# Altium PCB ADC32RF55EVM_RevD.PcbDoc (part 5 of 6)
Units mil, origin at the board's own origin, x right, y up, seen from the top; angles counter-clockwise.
Board outline 4190 x 2750 mil, 14 copper layers (Top Copper, Layer 2 (GND1), Layer 3 (PWR1), Layer 4 (GND2, Layer 5 (PWR2), Layer 6 (GND3), Layer 7 (SIG1), Layer 8 (GND4), Layer 9 (GND5), Layer 10 (SIG2), Layer 11 (GND6), Layer 12 (PWR3), Layer 13 (GND7), Bottom Copper), stack 58.6 mil thick; 427 components, 558 nets, 1902 pads, 1008 vias.
Unrouted connection lines stored in the file: 51.
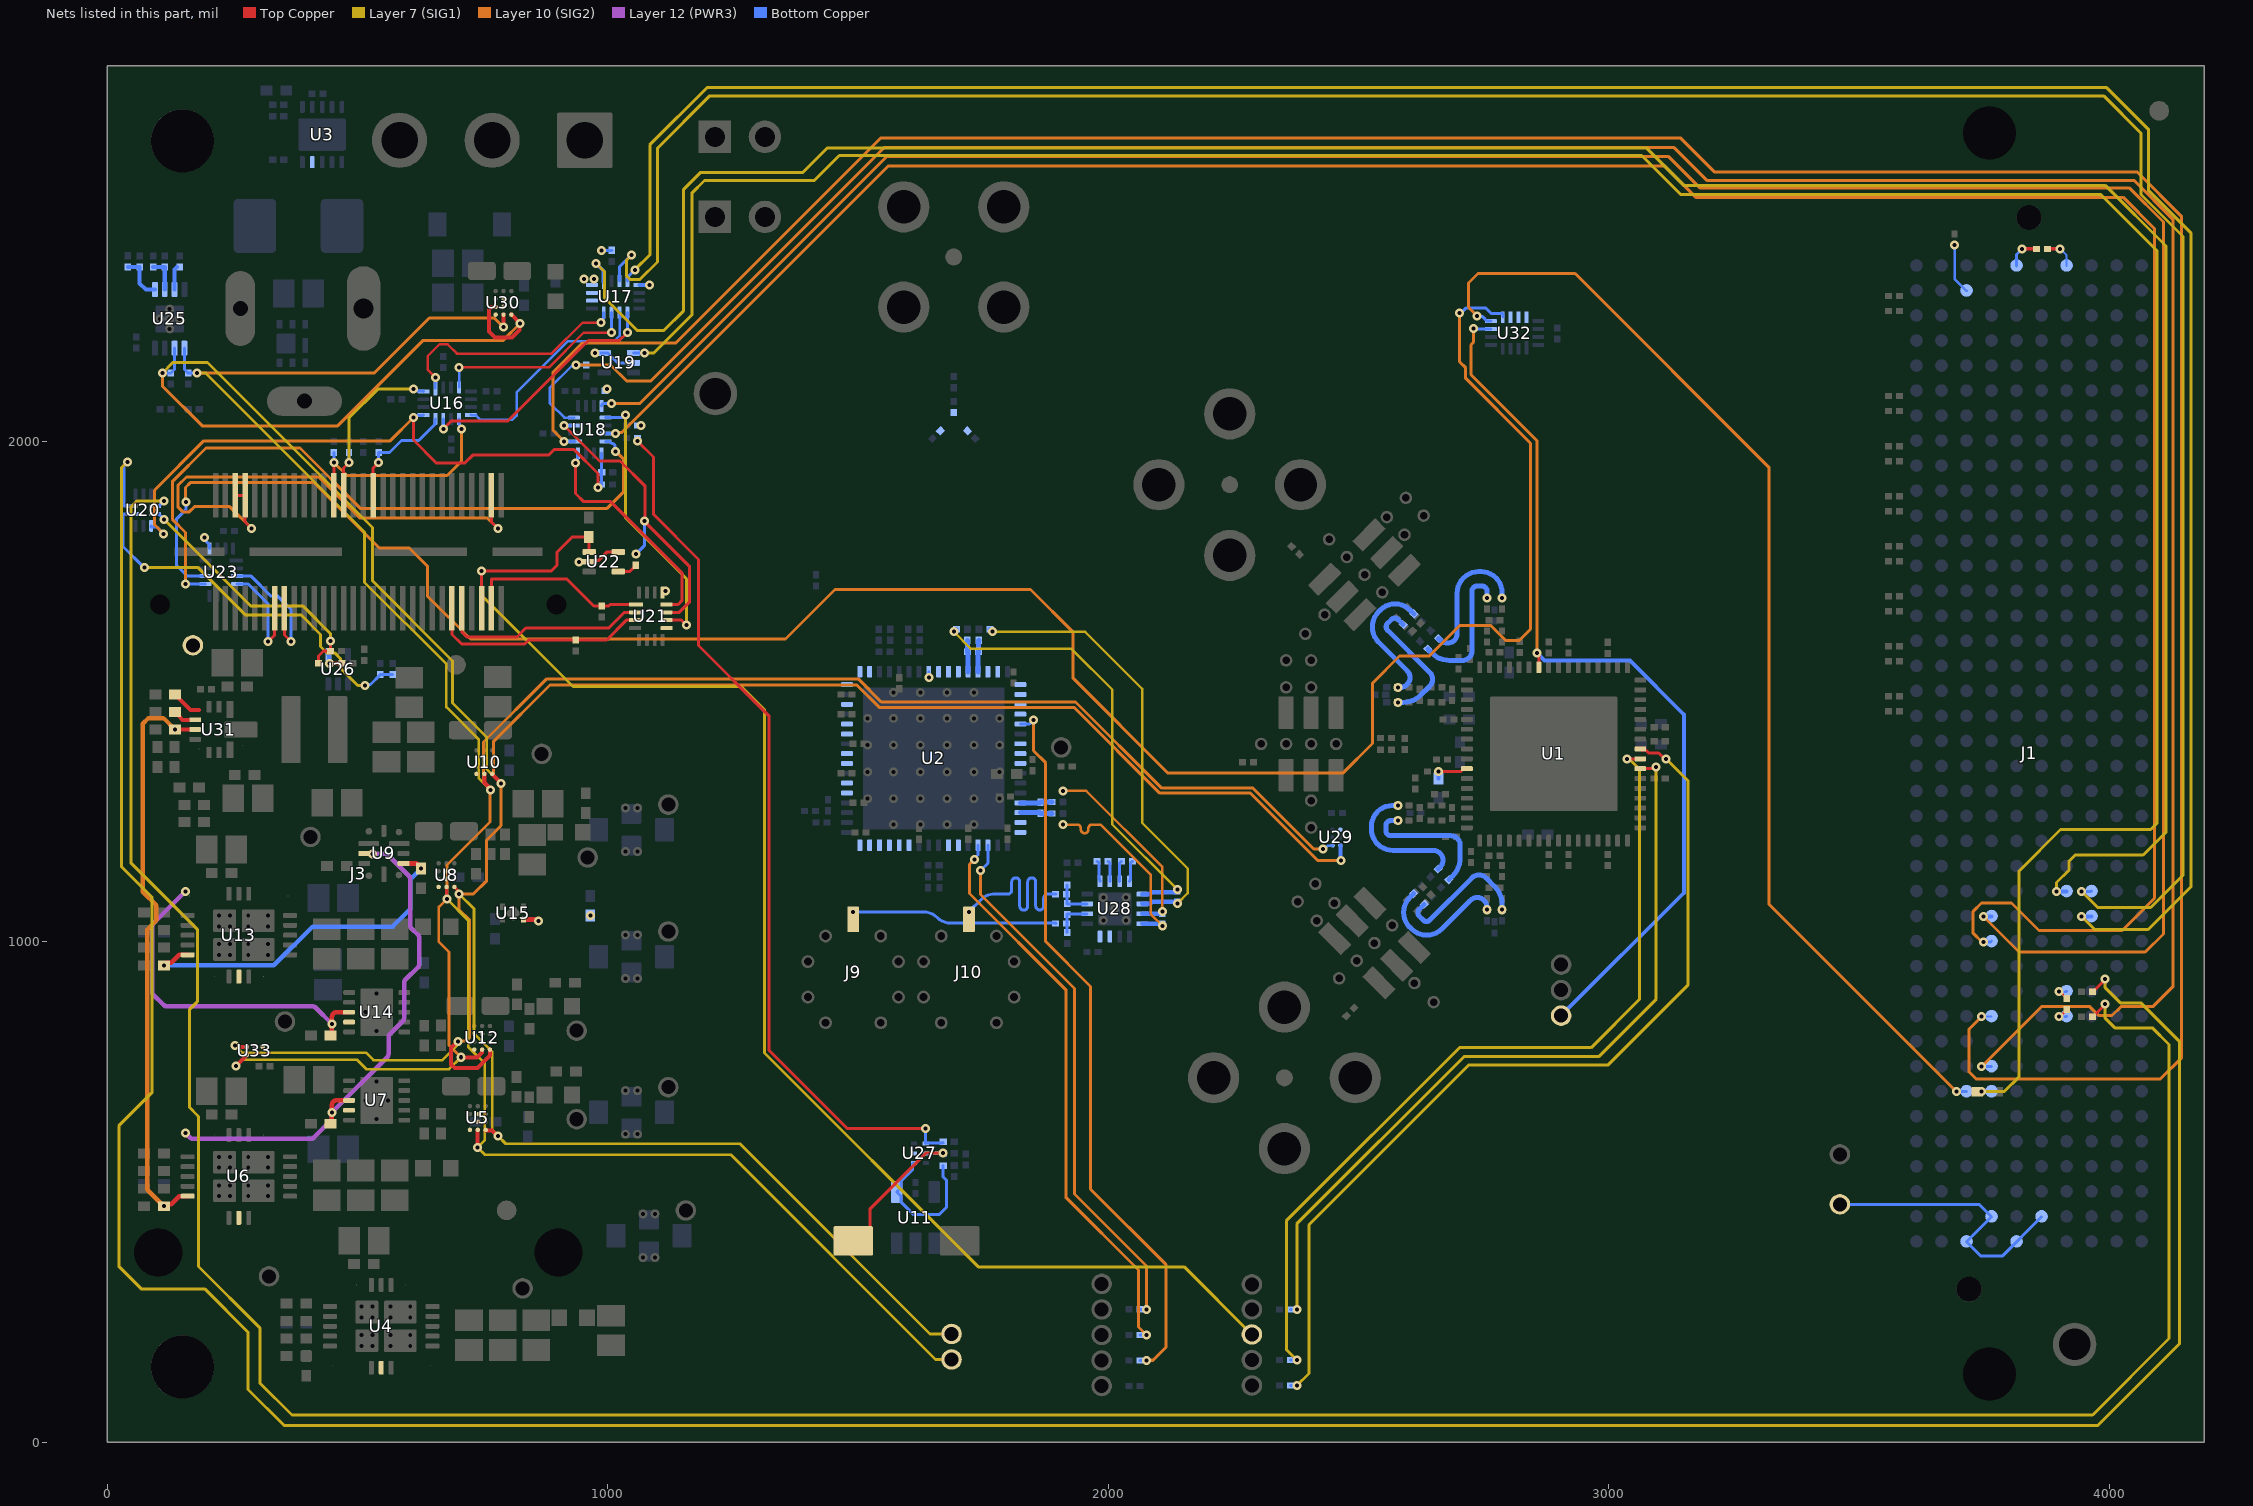
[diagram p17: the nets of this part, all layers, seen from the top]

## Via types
v1: diameter 18, hole 8, Top Copper to Bottom Copper, tented both sides, 1004 vias
v2: diameter 25.75, hole 15.75, Top Copper to Bottom Copper, tented both sides, 4 vias

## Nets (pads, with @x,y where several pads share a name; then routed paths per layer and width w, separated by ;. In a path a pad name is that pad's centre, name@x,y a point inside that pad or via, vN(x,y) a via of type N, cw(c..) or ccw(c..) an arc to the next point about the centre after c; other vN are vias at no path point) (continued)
NetR80_1: R80.1 R97.1 U26.4 | length 43
  Top Copper w8: v1(444,1555.95) R97.1@469,1555.95
  Bottom Copper w8: U26.4@441.63,1573 442.82,1571.82 442.82,1557.14 v1(444,1555.95)
NetR81_2: R81.2 R83.2 U16.13 U18.13 U20.8 | length 1281.3
  Top Copper w6: v1(612,2047.19) 612,2002 658,1956 714,1956 730,1972 881.63,1972 892.63,1983 933,1983 980.73,1935.27 v1(980.73,1907.18)
  Layer 10 (SIG2) w6: v1(112.29,1814.78) 94.22,1832.85 94.22,1901.8 192.88,2000.45 565.26,2000.45 v1(612,2047.19)
  Bottom Copper w6: U20.8@87.75,1830.5 87.75,1828.4 98.68,1828.4 v1(112.29,1814.78) ; v1(612,2047.19) 615.24,2047.19 619.31,2051.25 631.06,2051.25 U16.13@632,2052.19 ; R83.2@987.81,1913.48 987.93,1913.6 U18.13@987.93,1975.91
NetR88_1: R88.1 U22.4 | length 40.6
  Top Copper w6: U22.4@1021.13,1739.32 1044.13,1739.32 1056,1751.19 R88.1@1056,1751.98
NetR92_2: R92.2 R94.1 U25.1 | length 92.2
  Bottom Copper w8: R92.2@41.04,2348.24 41.12,2348.17 R94.1@64.84,2348.17 64.84,2315.16 76.94,2303.06 U25.1@95.16,2303.06
NetR93_2: R93.2 R95.1 U25.2 | length 68.1
  Bottom Copper w8: R93.2@91.79,2348.16 91.9,2348.06 R95.1@114.84,2348.06 U25.2@114.84,2303.06
NetR96_1: R96.1 U25.3 | length 47.1
  Bottom Copper w8: U25.3@134.53,2303.06 134.53,2343.06 R96.1@139.53,2348.06
NetR99_2: R99.2 R101.1 R102.2 | length 280.9
  Bottom Copper w10: R99.2@2638.68,1584.4 2646.51,1576.56 ccw(c2682.1,1612.15) 2682.1,1561.82 2706.54,1561.66 2706.96,1561.65 ccw(c2707.38,1580.94) 2726.67,1580.94 2726.67,1700.23 cw(c2736.67,1700.23) 2736.67,1710.23 2746.89,1710.23 cw(c2746.89,1700.23) 2756.89,1700.23 v1(2756.89,1686.4)
NetR105_1: R105.1 R106.2 R107.1 | length 281
  Bottom Copper w10: R106.2@2659.89,1605.61 2663.18,1602.32 ccw(c2677.89,1617.03) 2677.89,1596.23 ccw(c2677.89,1615.47) 2697.13,1615.47 2697.13,1696.06 cw(c2740.2,1696.06) 2740.2,1739.12 2745.22,1739.12 cw(c2745.22,1697.46) 2786.89,1697.46 v1(2786.89,1686.4)
NetR108_2: R108.2 R109.1 R110.2 | length 281
  Bottom Copper w10: R110.2@2578.04,1507.86 2582.69,1507.86 ccw(c2582.69,1528.66) 2597.4,1513.96 ccw(c2583.79,1527.56) 2597.4,1541.16 2540.41,1598.15 cw(c2570.87,1628.6) 2540.41,1659.06 2543.97,1662.61 cw(c2573.43,1633.15) 2602.89,1662.61 R108.2@2610.71,1654.79
  other v1: 2578.6,1508.11
NetR112_1: R112.1 R113.2 R114.1 | length 280.9
  Bottom Copper w10: R112.1@2578.04,1477.86 2589.12,1477.86 ccw(c2589.12,1528.19) 2624.7,1492.6 2642.1,1509.77 2642.4,1510.06 ccw(c2629.06,1524) 2642.7,1537.64 2558.35,1621.99 cw(c2565.42,1629.06) 2558.35,1636.13 2565.58,1643.36 cw(c2572.65,1636.28) 2579.72,1643.36 R113.2@2589.5,1633.58
  other v1: 2578.6,1478.11
NetR115_2: R115.2 R116.1 R117.2 | length 281
  Bottom Copper w10: v1(2578.6,1271.89) 2567.54,1271.89 ccw(c2567.54,1230.22) 2525.88,1230.22 2525.88,1225.2 ccw(c2568.94,1225.2) 2568.94,1182.13 2649.53,1182.13 cw(c2649.53,1162.89) 2668.77,1162.89 cw(c2647.97,1162.89) 2662.68,1148.18 R115.2@2659.39,1144.89
NetR120_1: R120.1 R121.2 R122.1 | length 280.9
  Bottom Copper w10: v1(2578.6,1241.89) 2564.77,1241.89 ccw(c2564.77,1231.89) 2554.77,1231.89 2554.77,1221.67 ccw(c2564.77,1221.67) 2564.77,1211.67 2684.06,1211.67 cw(c2684.06,1192.38) 2703.35,1191.96 2703.34,1191.54 2703.18,1167.1 cw(c2652.85,1167.1) 2688.44,1131.51 R121.2@2680.6,1123.68
NetR123_2: R123.2 R124.1 R125.2 | length 281
  Bottom Copper w10: R123.2@2610.21,1095.71 2602.39,1087.89 ccw(c2631.85,1058.43) 2602.39,1028.97 2605.94,1025.41 ccw(c2636.4,1055.87) 2666.85,1025.41 2723.84,1082.4 cw(c2737.44,1068.79) 2751.04,1082.4 cw(c2736.34,1067.69) 2757.14,1067.69 R125.2@2757.14,1063.04
  other v1: 2756.89,1063.6
NetR127_1: R127.1 R142.1 R143.2 U28.7 | length 77.5
  Bottom Copper w6: R143.2@1917.95,1112.68 1917.95,1094.68 R127.1@1917.95,1076.36 1917.95,1075.18 U28.7@1957.95,1075.18
NetR127_2: R127.2 R129.1 R144.2 U28.6 | length 77.5
  Bottom Copper w6: R144.2@1917.95,1017.99 1917.95,1035.99 R127.2@1917.95,1054.31 1917.95,1055.49 U28.6@1957.95,1055.49
NetR128_1: R128.1 U28.9 | length 42.1
  Bottom Copper w6: R128.1@1977.36,1160.46 1981.44,1157.16 1981.6,1154.92 cw(c1975.61,1154.5) 1981.61,1154.55 1981.81,1129.27 U28.9@1983.54,1120.46
NetR128_2: R128.2 U28.10 | length 41.9
  Bottom Copper w6: R128.2@1999.4,1160.46 1999.93,1160.46 2003.23,1157.16 U28.10@2003.23,1120.45
NetR130_1: R130.1 R131.2 R164.1 | length 280.9
  Bottom Copper w10: R131.2@2631.42,1074.5 2621.64,1064.72 ccw(c2628.72,1057.65) 2621.64,1050.58 2628.87,1043.35 ccw(c2635.94,1050.42) 2643.01,1043.35 2727.36,1127.7 cw(c2741,1114.06) 2754.94,1127.4 2755.23,1127.1 2772.4,1109.7 cw(c2736.81,1074.12) 2787.14,1074.12 R130.1@2787.14,1063.04
  other v1: 2786.89,1063.6
NetR132_1: R132.1 R134.2 R135.1
NetR133_1: R133.1 U11.4 U27.4 | length 289.6
  Bottom Copper w6: U27.4@1611.74,557.23 1609.77,557.23 1608.83,556.3 1608.83,544.06 1586.31,521.53 1586.31,508.31 U11.4@1577.5,499.5 1586.31,490.69 1586.31,479.11 1610.42,455 1663,455 1677,469 1677,523.16 1670.36,529.8 R133.1@1670.36,552.26
NetR141_1: R141.1 U28.11 | length 41.9
  Bottom Copper w6: U28.11@2022.92,1120.45 2022.92,1157.16 2026.22,1160.46 R141.1@2026.74,1160.46
NetR141_2: R141.2 U28.12 | length 42.5
  Bottom Copper w6: U28.12@2042.61,1120.46 2044.33,1123.16 ccw(c2038.6,1124.93) 2044.6,1124.93 2044.6,1154.77 cw(c2050.6,1154.74) 2044.61,1154.99 2044.7,1157.16 R141.2@2048.78,1160.46
NetR181_2: R181.2 U31.2 | length 47.5
  Top Copper w8: R181.2@135.46,1458.5 137.43,1458.5 143.28,1452.66 143.28,1450.69 150.78,1443.18 U31.2@175.46,1443.18
NetR182_2: R182.2 U31.1 | length 61.9
  Top Copper w8: R182.2@135.46,1493.5 137.43,1493.5 143.28,1487.66 143.28,1485.69 166.59,1462.37 U31.1@183.33,1462.37
NetU2_1: U2.1
NetU2_2: U2.2
NetU2_3: U2.3
NetU2_4: U2.4
NetU2_7: U2.7
NetU2_8: U2.8
NetU2_9: U2.9
NetU2_15: U2.15
NetU2_16: U2.16
NetU2_22: U2.22
NetU2_23: U2.23
NetU2_27: U2.27
NetU2_28: U2.28
NetU2_29: U2.29
NetU2_30: U2.30
NetU2_31: U2.31
NetU2_32: U2.32
NetU2_37: U2.37
NetU2_38: U2.38
NetU2_40: U2.40
NetU2_41: U2.41
NetU2_43: U2.43
NetU2_44: U2.44
NetU2_46: U2.46
NetU2_48: U2.48
NetU2_49: U2.49
NetU2_50: U2.50
NetU2_56: U2.56 | length 11.8
  Bottom Copper w5.5: v1(1641.47,1527.24) U2.56@1641.47,1539.05
NetU2_57: U2.57
NetU2_58: U2.58
NetU2_59: U2.59
NetU2_62: U2.62
NetU2_63: U2.63
NetU3_9: U3.9
NetU4_4: U4.4
NetU4_19: U4.19
NetU5_A3: U5.A3
NetU5_B2: U5.B2
NetU5_C2: U5.C2
NetU6_4: U6.4
NetU7_4: U7.4
NetU8_A3: U8.A3
NetU8_B2: U8.B2
NetU8_C2: U8.C2
NetU10_A3: U10.A3
NetU10_B2: U10.B2
NetU10_C2: U10.C2
NetU12_A3: U12.A3
NetU12_B2: U12.B2
NetU12_C2: U12.C2
NetU13_4: U13.4
NetU14_4: U14.4
NetU16_1: U16.1 U17.12 | length 483.1
  Top Copper w5: v1(655.62,2127.31) 640,2142.93 640,2169.49 664.13,2193.62 679.82,2193.62 698.43,2175 888,2175 949.98,2236.98 v1(987,2236.98)
  Bottom Copper w5: U16.1@655.62,2105.34 v1(655.62,2127.31)
  Bottom Copper w6: v1(987,2236.98) 987,2240.22 991.06,2244.29 991.06,2256.04 U17.12@992,2256.98
NetU16_4: U16.4 U17.11 | length 414
  Top Copper w5: v1(702.86,2147.31) 882.31,2147.31 951.98,2216.98 v1(1007.75,2216.98)
  Bottom Copper w5: U16.4@702.86,2107.31 v1(702.86,2147.31)
  Bottom Copper w6: v1(1007.75,2216.98) 1007.58,2217.14 1007.58,2230.26 1007.5,2230.35 1007.5,2256.72 U17.11@1007.75,2256.98
NetU16_8: U16.8 U17.10 | length 444.3
  Bottom Copper w5: U16.8@726.49,2052.19 727.42,2051.25 736.97,2051.25 746.03,2042.19 809.19,2042.19 818,2051 818,2097 921,2200 1013,2200 1023.5,2210.5 1023.5,2236.98 U17.10@1023.5,2256.98
NetU16_11: U16.11 U17.9 | length 507.9
  Top Copper w6: v1(671.37,2024.31) 687.37,2040.31 800.39,2040.31 961.06,2200.98 1023.24,2200.98 v1(1039.24,2216.98)
  Bottom Copper w6: v1(671.37,2024.31) U16.11@671.37,2044.31 ; v1(1039.24,2216.98) 1039.41,2217.14 1039.41,2230.26 1039.5,2230.35 1039.5,2256.72 U17.9@1039.24,2256.98
NetU21_9: U21.9
NetU27_5: U27.5
NetU28_3: U28.3
NetU28_4: U28.4
NetU29_C2: U29.C2
NetU30_A3: U30.A3
NetU30_B2: U30.B2
NetU30_C2: U30.C2
NetU32_10: U32.10
NetU32_11: U32.11
NetU32_12: U32.12
NetU33_C2: U33.C2
PG-2p1V: R33.1 U6.19 U7.3 U9.3 | length 1064.5
  Top Copper w9: R33.1@446.29,635.87 449,635.87 v1(449,658.81) 449,673.61 cw(c458,673.61) 458,682.61 U7.3@483.19,682.61 ; U9.3@513.36,1175.95 513.78,1175.53 529.47,1175.53 v1(529.93,1175.06)
  Layer 12 (PWR3) w9: v1(155.99,617.88) 165.58,608.29 ccw(c171.93,614.67) 171.93,605.67 405.83,605.67 ccw(c405.83,614.67) 412.2,608.3 446.38,642.48 ccw(c440,648.83) 449,648.83 v1(449,658.81) 559.36,769.17 ccw(c553,775.53) 562,775.53 562,808.53 cw(c571,808.53) 564.64,814.89 590.29,840.55 ccw(c583.93,846.91) 592.93,846.91 592.93,917.2 cw(c601.93,917.2) 595.55,923.55 620.96,948.96 ccw(c614.58,955.31) 623.58,955.31 623.58,972.95 623.58,1006.94 ccw(c614.58,1006.94) 620.97,1013.29 607.64,1026.62 cw(c614,1032.98) 605,1032.98 605,1125.17 ccw(c596,1125.17) 602.36,1131.54 561.46,1172.44 ccw(c555.11,1166.06) 555.11,1175.06 v1(529.93,1175.06)
PG-2p7V: R100.1 U13.19 U14.3 | length 694.6
  Top Copper w9: R100.1@446.29,812.12 449,812.12 v1(449,835.06) 449,849.87 cw(c458,849.87) 458,858.87 U14.3@483.19,858.87
  Layer 12 (PWR3) w9: v1(156,1100.07) 92.06,1036.14 ccw(c98.43,1029.78) 89.43,1029.78 89.43,900.3 ccw(c98.43,900.3) 92.06,893.94 112.69,873.31 ccw(c119.05,879.68) 119.05,870.68 410,870.68 cw(c410,861.68) 416.37,868.04 449,835.41 v1(449,835.06)
PG-AVDD12: R23.1 R31.2 U9.8 U13.24 | length 724.8
  Top Copper w9: R31.2@113.07,953.45 117.12,957.51 127.63,957.51 143.58,973.45 U13.24@160.57,973.45
  Top Copper w10: U9.8@592.1,1156.26 616.78,1156.26 620.29,1152.76 622.25,1152.76 627.1,1147.92 v1(627.1,1145.95)
  Bottom Copper w9: v1(113.07,952.51) 332.85,952.51 410.34,1030 570,1030 605.15,1065.15 605.15,1124 v1(627.1,1145.95)
PG-C2M: J1.D1 R67.2 | length 64.4
  Top Copper w7: R67.2@3876.99,2384 v1(3902,2384)
  Bottom Copper w4: v1(3902,2384) 3915,2371 J1.D1@3915,2350
PG-DVDD12: R11.2 R155.1 U6.24 U31.3 | length 1171.1
  Top Copper w8: v1(135.46,1423.5) U31.3@175.46,1423.5
  Top Copper w9: v1(113.07,471.26) 117.12,475.31 127.63,475.31 143.58,491.26 U6.24@160.57,491.26
  Layer 10 (SIG2) w9: v1(113.07,471.26) 80,504.33 80,1024 98.28,1042.28 98.28,1072.72 71.14,1099.86 71.14,1435.52 82.32,1446.7 112.27,1446.7 v1(135.46,1423.5)
PG-M2C: J1.F1 R67.1 | length 63.6
  Top Copper w7: v1(3826,2384) R67.1@3851.01,2384
  Bottom Copper w6: J1.F1@3815,2350 3815,2373 v1(3826,2384)
PRSNT-M2C-L: J1.H2 R140.2 | length 101.9
  Bottom Copper w5: v1(3691,2392) 3691,2324 J1.H2@3715,2300
RPI_LOAD_FT: J3.3 J3.53 J3.55 | length 1069.2
  Top Copper w6: J3.55@255.69,1891.59 J3.53@275.37,1891.59 275.37,1838.2 v1(288.41,1825.16) ; J3.3@767.5,1891.59 767.5,1838.2 v1(780.54,1825.16)
  Layer 10 (SIG2) w6: v1(288.41,1825.16) 244.57,1869 174.23,1869 163.94,1858.71 150.98,1858.71 141,1868.7 141,1911.18 158.14,1928.32 422.68,1928.32 504.19,1846.81 758.89,1846.81 v1(780.54,1825.16)
RSTb_ADC: R24.2 R62.2 U27.1 | length 1769.4
  Top Copper w6: v1(1059.66,1999.87) 1091.2,1968.32 1091.2,1853.73 1181.37,1763.56 1181.37,1591.63 1321.72,1451.28 1321.72,783.28 1478.4,626.6 v1(1635.36,626.6)
  Bottom Copper w6: v1(1635.36,626.6) U27.1@1635.36,596.6 1636.19,597.43 1669.53,597.43 R24.2@1670.36,598.26
RSTb_ADC_FMC: J1.G28 U18.11 | length 5213.1
  Layer 10 (SIG2) w6: v1(1015.81,2015.28) 1017.38,2016.85 1027.7,2016.85 1560.84,2550 3110.97,2550 3173.97,2487 4028,2487 4090.64,2424.36 4090.64,1086.64 4026,1022 3860,1022 3805,1077 3745.01,1077 3728.37,1060.36 3728.37,1016.63 3745.74,999.26 v1(3749.35,999.26)
  Bottom Copper w6: U18.11@995.81,2015.28 v1(1015.81,2015.28) ; v1(3749.35,999.26) 3763.26,999.26 J1.G28@3765,1001
RSTb_ADC_FT: J3.48 U23.4 | length 225.2
  Top Copper w6: v1(321.39,1599.57) 334.43,1612.61 J3.48@334.43,1666
  Bottom Copper w6: U23.4@259.5,1714.38 281.62,1714.38 321.39,1674.61 v1(321.39,1599.57)
RSTb_ADC_USB: U18.12 U23.9 | length 1373.1
  Layer 10 (SIG2) w6: v1(156.5,1714.38) 156.5,1817.5 130.02,1843.98 130.02,1918.87 197.18,1986.03 385.28,1986.03 506.42,1864.9 997.9,1864.9 1031.81,1898.81 1031.81,1963.53 v1(1015.81,1979.54)
  Bottom Copper w6: v1(156.5,1714.38) U23.9@196.5,1714.38 ; U18.12@995.81,1999.54 1003.68,1999.54 1004.62,1998.6 1004.62,1998.51 1008.13,1995 1010.79,1995 1014.3,1991.49 1014.3,1985.08 1017.65,1981.73 1018,1981.73 v1(1015.81,1979.54)
RSTb_MANUAL: R25.2 SW3.2 U27.2 | length 309.3
  Top Copper w6: SW3.2@1490.7,402 1497.74,402 1524.27,428.53 1524.27,466.27 1635.26,577.26 v1(1670.36,577.26)
  Bottom Copper w6: U27.2@1635.56,576.92 1635.73,577.09 1670.19,577.09 v1(1670.36,577.26)
SCL_FMC: R71.2 U20.2 | length 7007.7
  Top Copper w6: R71.2@3967.05,900 3967.83,900 3992.05,924.21 v1(3992.05,925)
  Layer 7 (SIG1) w6: v1(40.63,1958.72) 28,1946.09 28,1150 89.7,1088.3 89.7,698.7 23,632 23,351 67.74,306.26 194.7,306.26 281.39,219.57 281.39,105 353.39,33 3977.26,33 4141,196.74 4141,800 4063.3,877.7 4022.3,877.7 3992.05,907.95 v1(3992.05,925)
  Bottom Copper w6: v1(40.63,1958.72) 33.16,1951.25 33.16,1869.87 U20.2@48.38,1869.87
SCL_I2C: PP26.1 R73.2 U5.A1 U8.A1 U10.A1 U12.A1 U25.6 U29.A2 U30.A1 U30.B3 U33.A2 | length 7197.5
  Top Copper w6: U8.A1@693.68,1109.14 693.68,1108.37 700.7,1101.35 700.7,1097.6 v1(702.99,1095.3)
  Top Copper w8: v1(255,792) 257.71,792 259.96,789.75 U33.A2@279,789.75 ; v1@700.74,799.83 v1(700.34,800.23) 687.07,786.95 687.07,754.51 694.34,747.23 739.32,747.23 764.63,772.54 U12.A1@764.63,784.08 ; U5.A1@756.19,622.88 768.5,622.88 779.97,611.4 v1(780.48,611.4) ; U10.A1@769.18,1334.96 769.18,1334.73 786.65,1317.26 v1(786.65,1315.96) ; U30.B3@775.93,2268.35 775.76,2268.18 767.92,2268.18 762.53,2262.8 762.53,2219.14 774.29,2207.38 808.51,2207.38 823.58,2222.44 823.58,2233.76 v1(824.77,2234.95) ; U30.A1@807.43,2252.6 v1@824.92,2235.1
  Layer 10 (SIG2) w6: v1(110,2136) 110,2110.19 189.56,2030.64 460.26,2030.64 631.12,2201.49 791.31,2201.49 v1(824.77,2234.95) ; v1(700.34,800.23) 701.46,801.34 717.04,801.34 724.03,808.34 724.03,1042.97 702.99,1064.01 v1(702.99,1095.3) 731.97,1095.3 758,1121.33 758,1203 786.65,1231.65 v1(786.65,1315.96) 771.42,1331.18 771.42,1399.42 884.76,1512.76 1497.75,1512.76 1542.5,1468.02 1931.55,1468.02 2103,1296.57 2284.16,1296.57 2418.98,1161.75 v1(2465.3,1161.75)
  Layer 7 (SIG1) w5.5: v1(110,2136) 130.88,2156.88 200.49,2156.88 529.98,1827.39 529.98,1720.98 690,1560.96 690,1476.82 758.11,1408.71 758.11,1344.5 v1(786.65,1315.96) ; v1(255,792) 269,778 517,778 532,763 669.47,763 697.95,791.48 697.95,797.84 v1(700.34,800.23) ; v1(702.99,1095.3) 732.66,1065.63 732.66,816.34 769,780 769,624.82 780.48,613.34 780.48,611.9 796.26,596.12 1263.88,596.12 1644,216 PP26.1@1687,216
  Bottom Copper w5.5: v1(110,2136) 110.2,2135.8 R73.2@127.03,2135.8 134.53,2143.3 U25.6@134.53,2185.8
  Bottom Copper w8: U29.A2@2464,1192.25 2464,1163.05 ccw(c2465.3,1163.05) v1(2465.3,1161.75)
SCL_USB: R90.1 R91.2 U20.1 | length 771.9
  Layer 7 (SIG1) w6: v1(74,1747) 181.52,1747 275.61,1652.91 387.09,1652.91 426.2,1613.8 426.2,1589.74 438.99,1576.95 454.26,1576.95 466.43,1564.78 466.43,1545.7 500.6,1511.53 v1@514.47,1511.53
  Bottom Copper w6: U20.1@50.35,1854.13 31.52,1854.13 31.52,1789.51 v1(74,1747) ; v1(514.98,1511.53) 517.28,1513.82 525.93,1513.82 545.28,1533.17 R90.1@545.28,1533.95 R91.2@570.28,1533.95
SCLK_ADC: R58.2 U1.55 | length 1585.1
  Top Copper w6: U1.55@3063.23,1345.47 3091.47,1345.47 v1(3095,1349)
  Layer 7 (SIG1) w6: v1(2376.95,264.77) 2376.95,435.95 2711,770 2980.02,770 3095,884.98 v1(3095,1349)
  Bottom Copper w6: R58.2@2364.28,264.77 v1(2376.95,264.77)
SCLK_ADC_FMC: J1.G31 U18.1 | length 5952
  Layer 10 (SIG2) w6: v1(912.82,1999.54) 890.72,2021.63 890.72,2137.72 949.12,2196.12 1136.12,2196.12 1546,2606 3143,2606 3211,2538 4055.41,2538 4145.05,2448.36 4145.05,768.05 4102.79,725.79 3734.1,725.79 3720.05,739.84 3720.05,825.05 v1(3745,850)
  Bottom Copper w4: v1(3745,850) J1.G31@3765,850
  Bottom Copper w6: v1(912.82,1999.54) U18.1@934.78,1999.54
SCLK_ADC_FT: J3.4@767.5,1666 R85.2 U21.1 | length 370.5
  Top Copper w6: J3.4@767.5,1666 767.5,1724 918.68,1724 972.21,1670.47 R85.2@988.21,1670.47 1001.81,1670.47 1004.95,1673.62 U21.1@1056.47,1673.62
SCLK_ADC_USB: U18.16 U21.12 | length 450.1
  Top Copper w6: v1(935.69,1955.91) 935.69,1895.31 952,1879 1006,1879 1148,1737 1148,1681 1140.62,1673.62 U21.12@1117.5,1673.62
  Bottom Copper w6: v1(935.69,1955.91) 935.69,1959.16 939.75,1963.22 939.75,1974.98 U18.16@940.69,1975.91
SCLK_LMK: R45.2 U2.19 | length 1083.5
  Layer 10 (SIG2) w6: v1(1745,1142) 1745,1093.9 1746.73,1092.17 1932.59,906.3 1932.59,495.41 2076.34,351.66 v1(2076.34,265.05)
  Bottom Copper w6: v1(1745,1142) 1759.58,1156.58 U2.19@1759.58,1192.6 ; R45.2@2063.67,265.05 v1(2076.34,265.05)
SCLK_LMK_FMC: J1.D26 R53.1 U17.1 | length 5120.7
  Layer 7 (SIG1) w6: v1(976.55,2355.13) 993.85,2337.83 993.85,2286.15 1058.96,2221.04 1112.13,2221.04 1151.77,2260.68 1151.77,2503.08 1185.69,2537 1390,2537 1439.04,2586.04 3074.93,2586.04 3149.81,2511.17 3992.13,2511.17 4113.44,2389.85 4113.44,1218.44 4068,1173 3932,1173 3920,1161 3920,1143 3895,1118 v1(3895,1100)
  Bottom Copper w8: v1(976.55,2355.13) 992,2339.68 U17.1@992,2318 ; v1(3895,1100) J1.D26@3915,1100
SCLK_LMK_USB: J3.33 R42.1 U16.16 | length 354.1
  Top Copper w6: J3.33@472.22,1891.59 472.22,1946.16 v1(483.13,1957.07)
  Layer 7 (SIG1) w6: v1(483.13,1957.07) 483.13,2046.13 541.43,2104.43 v1(612,2104.43)
  Bottom Copper w6: v1(483.13,1957.07) R42.1@483.13,1977.07 ; v1(612,2104.43) 615.24,2104.43 619.31,2100.37 631.06,2100.37 U16.16@632,2099.43
SDA_FMC: R72.2 U20.6 | length 6668.9
  Top Copper w6: R72.2@3967.05,850 3967.83,850 3992.05,874.21 v1(3992.05,875)
  Layer 7 (SIG1) w6: v1(113.58,1880.59) 59.44,1880.59 46.98,1868.12 46.98,1157.48 180,1024.45 180,880 164.72,864.72 164.72,668.28 180.48,652.52 cw(c176.2,648.31) 182.2,648.31 182.2,350.95 304.79,228.36 304.79,118.21 369,54 3967,54 4119.75,206.75 4119.75,794.25 4086.3,827.7 4011.39,827.7 3992.05,847.05 v1(3992.05,875)
  Bottom Copper w6: U20.6@95.62,1869.87 102.87,1869.87 v1(113.58,1880.59)
SDA_I2C: PP27.1 R77.2 U5.A2 U8.A2 U10.A2 U12.A2 U25.5 U29.A1 U30.A2 U33.A1 | length 6747.4
  Top Copper w6: U8.A2@677.93,1109.14 678.3,1108.77 678.3,1085.47 v1(678.67,1085.1)
  Top Copper w8: v1(256.81,751.12) 256.81,751.52 279,773.71 U33.A1@279,774 ; v1(706.73,768.87) 707.38,768.23 738.34,768.23 748.88,778.76 U12.A2@748.88,784.08 ; v1(739.91,588.28) 740.18,588.55 740.18,623.61 U5.A2@740.44,623.88 ; U10.A2@753.43,1334.96 753.43,1318.03 765.66,1305.79 v1(765.66,1303.09) ; v1@791.68,2227.86 U30.A2@791.68,2252.6
  Layer 10 (SIG2) w5.5: v1(678.67,1085.1) 662.47,1068.9 662.47,999.53 682.78,979.22 682.78,792.83 v1(706.73,768.87)
  Layer 10 (SIG2) w6: v1(179,2136) 533.59,2136 643.48,2245.9 773.42,2245.9 v1(791.46,2227.86) ; v1(678.67,1085.1) 678.67,1153.05 764.68,1239.06 v1@764.68,1304.07 ; v1(765.66,1303.09) v1@764.68,1304.07 ; v1(2429,1185) 2410.81,1185 2289.24,1306.57 2107.14,1306.57 1934.85,1478.87 1546.57,1478.87 1500.3,1525.14 878.14,1525.14 751.86,1398.86 751.86,1316.89 v1@764.68,1304.07
  Layer 7 (SIG1) w5.5: v1(179,2136) 196.57,2136 514.17,1818.39 514.17,1717.82 677.48,1554.51 677.48,1468.89 742.14,1404.22 742.14,1326.61 v1(765.66,1303.09) ; v1(256.81,751.12) 269.69,764 498.5,764 517.5,745 682.86,745 v1(706.73,768.87) ; 721.28,1042.48 721.28,789.33 754.39,756.23 754.39,603.48 739.91,589 739.91,588.78 754.69,574 1246,574 1655,165 PP27.1@1687,165
  Layer 7 (SIG1) w6: v1(678.67,1085.1) 721.28,1042.48
  Bottom Copper w5.5: v1(2429,1185) 2432.38,1185 2438.95,1191.57 2447.57,1191.57 U29.A1@2448.25,1192.25
  Bottom Copper w6: U25.5@154.21,2185.8 154.21,2143.3 R77.2@161.71,2135.8 161.91,2136 v1(179,2136)
SDA_USB: R55.2 R80.2 U20.7 | length 526.7
  Top Copper w6: R80.2@421.95,1555.95 421.95,1570.76 431.82,1580.62 R55.2@445.8,1580.62 445.9,1580.72 445.9,1600.9 v1(446,1601)
  Layer 7 (SIG1) w6: v1(113.58,1843.41) 286.2,1670.8 390.36,1670.8 446,1615.15 v1(446,1601)
  Bottom Copper w6: U20.7@95.62,1854.13 102.87,1854.13 v1(113.58,1843.41)
SDI_ADC_FMC: J1.G34 R75.1 U19.1 | length 5407.1
  Layer 7 (SIG1) w6: v1(1073.56,2176.27) 1092.15,2176.27 1168,2252.12 1168,2495.49 1193.32,2520.8 1412.8,2520.8 1462.71,2570.71 3065.99,2570.71 3144.27,2492.43 3983.57,2492.43 4096,2380 4096,1237 4083,1224 3903,1224 3820.13,1141.13 3820.13,730.13 3790,700 v1(3745,700)
  Bottom Copper w6: U19.1@1051.24,2176.1 1051.24,2176.27 v1(1073.56,2176.27) ; v1(3745,700) J1.G34@3765,700
SDI_FT: J3.6 PP28.1 R79.1 U22.1 | length 2963.3
  Top Copper w6: J3.6@747.81,1666 v1(747.81,1740.82) 887.4,1740.82 898.66,1752.09 898.66,1778.02 928.77,1808.12 R79.1@962.1,1808.12 962.87,1807.36 U22.1@962.87,1778.69
  Layer 7 (SIG1) w6: v1(747.81,1740.82) 747.81,1692.19 930.5,1509.5 1266.84,1509.5 1313.07,1463.27 1313.07,777.55 1740.51,350.11 2151.89,350.11 PP28.1@2287,215
SDI_LMK: R48.2 U2.20 | length 1144.6
  Layer 10 (SIG2) w6: v1(1732.4,1163.9) 1732.4,1163.78 1723,1154.38 1723,1096 1916,903 1916,488 2060.34,343.66 2060.34,230.05 v1(2076.34,214.05)
  Bottom Copper w6: v1(1732.4,1163.9) 1732.4,1165.46 1739.9,1172.96 U2.20@1739.9,1192.6 ; R48.2@2063.67,214.05 v1(2076.34,214.05)
SDI_LMK_FMC: J1.C26 R54.1 U17.3 | length 5233
  Layer 7 (SIG1) w6: v1(1047.18,2371.63) 1047.18,2371.15 1037.02,2360.99 1037.02,2330.58 1044.39,2323.22 1064.47,2323.22 1099.29,2358.04 1099.29,2585.29 1203.81,2689.81 3989.19,2689.81 4063.79,2615.21 4063.79,2492.56 4147.49,2408.86 4147.49,1132.49 4083,1068 3977,1068 v1(3945,1100)
  Bottom Copper w6: U17.3@1023.5,2319.97 1023.5,2348.51 1046.62,2371.63 v1(1047.18,2371.63) ; v1(3945,1100) 3964,1100 J1.C26@3965,1101
SDI_LMK_USB: J3.35 R43.1 U16.9 | length 450.1
  Top Copper w6: J3.35@452.54,1891.59 v1@452.54,1957.31
  Layer 10 (SIG2) w6: v1(452.65,1957.42) 478.78,1931.3 679.3,1931.3 707.86,1959.86 v1(707.86,2024.31)
  Bottom Copper w6: v1(452.65,1957.42) R43.1@452.65,1977.42 ; U16.9@702.86,2044.31 703.8,2043.38 703.8,2031.62 707.86,2027.56 v1(707.86,2024.31)
SDIO_ADC: R59.2 U1.56 | length 1707.3
  Top Copper w6: v1(3037,1365.16) U1.56@3063.23,1365.16
  Layer 7 (SIG1) w6: v1(2376.95,163.77) 2356,184.72 2356,442 2702,788 2965,788 3061.16,884.16 3061.16,1344.76 3040.77,1365.16 v1(3037,1365.16)
  Bottom Copper w6: R59.2@2364.28,163.77 v1(2376.95,163.77)
SDIO_ADC_FMC: J1.G33 R60.2 U18.4 | length 5656.6
  Layer 10 (SIG2) w6: v1(937.02,2152.13) 1005.66,2152.13 1037.79,2120 1086,2120 1553,2587 3130,2587 3196,2521 4049.46,2521 4127.93,2442.53 4127.93,910.6 4087.33,870 4023.62,870 4005.86,852.25 3979.24,852.25 3961.49,870 3865,870 v1(3745,750)
  Bottom Copper w5: U18.4@932.82,2046.78 913.27,2046.78 886.93,2073.12 884,2076.05 884,2106 927.64,2149.64 934.54,2149.64 v1(937.02,2152.13)
  Bottom Copper w6: v1(937.02,2152.13) R60.2@957.02,2152.13 ; v1(3745,750) J1.G33@3765,750
SDIO_ADC_USB: R88.2 U18.3 U21.11 | length 628.5
  Top Copper w6: v1(912.82,2031.03) 983.55,1960.3 1024.7,1960.3 1074,1911 1074,1841 v1(1073,1840) 1163,1750 1163,1678 1142.88,1657.87 U21.11@1117.5,1657.87
  Bottom Copper w6: v1(912.82,2031.03) U18.3@932.82,2031.03 ; v1(1056,1774.02) 1073,1791.02 v1(1073,1840)
SDO_FT: J3.10 U21.2 | length 418.1
  Top Copper w6: J3.10@708.44,1666 708.44,1618.56 718.51,1608.49 818.47,1608.49 836.36,1626.38 962.21,1626.38 1002.1,1626.38 1033.5,1657.78 1054.41,1657.78 U21.2@1054.5,1657.87
SDO_LMK: R49.2 U2.5 | length 1454.2
  Layer 10 (SIG2) w6: v1(1850.69,1442.34) 1850.69,1381.43 1875,1357.12 1875,1000.14 1964.79,910.35 1964.79,505.21 2114.99,355.01 2114.99,188.91 2089.53,163.45 2076.73,163.45 v1(2076.34,163.05)
  Bottom Copper w6: U2.5@1824.54,1434.72 1843.08,1434.72 v1(1850.69,1442.34) ; R49.2@2063.67,163.05 v1(2076.34,163.05)
SDO_LMK_FMC: J1.C27 U17.4 | length 5200.8
  Layer 7 (SIG1) w6: v1(1054.15,2342.14) 1084.07,2372.06 1084.07,2592.07 1198.1,2706.1 3995.18,2706.1 4079,2622.28 4079,2500.21 4164.03,2415.19 4164.03,1110.03 4078,1024 3971,1024 v1(3945,1050)
  Bottom Copper w6: U17.4@1039.24,2319.97 1039.24,2327.84 1040.18,2328.78 1040.8,2328.78 v1(1054.15,2342.14)
  Bottom Copper w8: v1(3945,1050) J1.C27@3965,1050
SDO_LMK_USB: J3.27 R44.1 U16.12 | length 237
  Top Copper w6: J3.27@531.28,1891.59 531.28,1946.16 v1(542.18,1957.07)
  Bottom Copper w6: v1(542.18,1957.07) R44.1@542.18,1977.07 563.86,1977.07 588.02,2001.22 622.22,2001.22 654.68,2033.68 654.68,2043.38 U16.12@655.62,2044.31
SEN_ADC: R61.2 U1.57 | length 1829.4
  Top Copper w6: U1.57@3063.23,1384.84 3065.15,1382.92 3074,1382.92 3080.16,1376.77 3099.86,1376.77 3111.45,1365.18 v1(3114.7,1365.18)
  Layer 7 (SIG1) w6: v1(2376.95,112.77) 2401,136.82 2401,434 2720,753 2998.15,753 3158,912.85 3158,1321.88 v1(3114.7,1365.18)
  Bottom Copper w6: R61.2@2364.05,113 2364.28,112.77 v1(2376.95,112.77)
SEN_ADC_FMC: J1.G27 U18.8 | length 5224.2
  Layer 10 (SIG2) w6: v1(1007.93,2075.4) 1064.32,2075.4 1557.92,2569 3119,2569 3182,2506 4040,2506 4108.37,2437.63 4108.37,1015.37 4072.07,979.07 3819.93,979.07 v1(3749,1050)
  Bottom Copper w6: U18.8@987.93,2070.4 cw(c992.93,2070.4) 992.93,2075.4 v1(1007.93,2075.4)
  Bottom Copper w8: v1(3749,1050) J1.G27@3765,1050
SEN_ADC_FT: J3.12 R84.1 U21.3 | length 445.7
  Top Copper w6: J3.12@688.76,1666 688.76,1613.75 708.04,1594.46 834.02,1594.46 842.31,1602.76 R84.1@936.21,1602.76 997.82,1602.76 1037.19,1642.13 U21.3@1054.5,1642.13
SEN_ADC_USB: U18.9 U21.10 | length 556.3
  Top Copper w6: U21.10@1117.5,1642.13 1147.5,1642.13 v1(1157.5,1632.13)
  Layer 7 (SIG1) w6: v1(1035.81,2051.78) 1035.81,1846.61 1157.5,1724.92 v1(1157.5,1632.13)
  Bottom Copper w6: U18.9@995.81,2046.78 1027.56,2046.78 1032.56,2051.78 v1(1035.81,2051.78)
SPISEL_ADC: PP25.1 U1.10 U32.7 | length 1818
  Top Copper w6: v1(2856.47,1576.24) 2856.47,1575.45 2860.47,1571.45 U1.10@2860.47,1548.23
  Layer 10 (SIG2) w6: v1(2730,2225) 2730,2197.63 2724.76,2192.39 2724.76,2132.84 2856.47,2001.13 v1(2856.47,1576.24)
  Bottom Copper w6: v1(2730,2225) 2731.06,2223.94 2764.69,2223.94 U32.7@2764.76,2223.87
  Bottom Copper w8: v1(2856.47,1576.24) 2871.5,1561.21 3042.79,1561.21 3150,1454 3150,1097 PP25.1@2905,852
SPISEL_ADC_FMC: J1.H34 U32.8 | length 2296.3
  Layer 10 (SIG2) w6: v1(2737.09,2250.41) 2720,2267.5 2720,2316 2739,2335 2933,2335 3320,1948 3320,1075 v1(3695,700)
  Bottom Copper w6: v1(2737.09,2250.41) 2739,2248.5 2748.13,2248.5 2757.01,2239.62 U32.8@2764.76,2239.62 ; v1(3695,700) J1.H34@3715,700
SPISEL_ADC_FT: J3.46 U23.3 | length 271.2
  Top Copper w6: J3.46@354.11,1666 354.11,1612.61 v1(367.15,1599.57)
  Bottom Copper w6: U23.3@259.5,1730.13 287.47,1730.13 327.33,1690.26 340.74,1690.26 367.15,1663.85 v1(367.15,1599.57)
SPISEL_ADC_USB: U23.10 U32.9 | length 4341.8
  Layer 10 (SIG2) w6: v1@157,1878.05 156.32,1878.72 156.32,1907.38 165.95,1917 413,1917 543.87,1786.13 603.87,1786.13 640,1750 640,1690 725.55,1604.45 1355.09,1604.45 1453.99,1703.35 1844.94,1703.35 1930,1618.28 1930,1526.14 2119.57,1336.57 2468.57,1336.57 2528,1396 2528,1516.44 2582.15,1570.59 2641.59,1570.59 2703,1632 2764,1632 2794,1602 2821.79,1602 2844,1624.21 2844,1995.62 2714.17,2125.45 2714.17,2146.46 2702,2158.63 v1(2702,2256)
  Bottom Copper w6: v1(157,1878.19) 157,1863 138,1844 138,1752.45 160.33,1730.13 U23.10@196.5,1730.13 ; v1(2702,2256) 2705.25,2256 2715.66,2266.41 2753.9,2266.41 2764.99,2255.32 2787.44,2255.32 2788.38,2254.39 U32.9@2788.38,2247.5
SYSREF_ADC_N: R146.2 R162.1 U28.16 | length 393.1
  Layer 10 (SIG2) w5: v1(1909.59,1233.85) 1920.31,1233.85 1937.81,1233.85 cw(c1937.81,1226.35) 1945.31,1226.35 1945.31,1223.83 ccw(c1952.81,1223.83) 1960.31,1223.83 1960.31,1226.35 cw(c1967.81,1226.35) 1967.81,1233.85 1980.37,1233.85 1984.85,1233.85 2085.32,1133.38 2085.32,1054.49 v1(2108.19,1031.62)
  Bottom Copper w9: U28.16@2068.19,1035.8 2104.01,1035.8 cw(c2104.01,1031.62) v1(2108.19,1031.62)
SYSREF_ADC_P: R147.2 R162.2 U28.15 | length 393.1
  Layer 10 (SIG2) w5: v1(1909.59,1300.95) 1956.05,1300.95 2108.19,1148.81 v1(2108.19,1059.67)
  Bottom Copper w9: U28.15@2068.19,1055.49 2104.01,1055.49 ccw(c2104.01,1059.67) v1(2108.19,1059.67)
SYSREF_FPGA_N: R157.2 R163.1 U28.14 | length 897.9
  Layer 7 (SIG1) w5: v1(1768.6,1619.1) 1953.9,1619.1 2068,1505 2068,1237 2159,1146 2159,1096.81 v1(2138.19,1076)
  Bottom Copper w9: R157.2@1763.6,1624.1 v1(1768.6,1619.1) ; U28.14@2068.19,1075.18 2079.14,1075.18 ccw(c2079.14,1084.18) 2084.27,1076.79 2085.6,1077.71 cw(c2090.73,1070.31) 2090.73,1079.31 R163.1@2133.14,1079.31 ; v1(2138.19,1076) R163.1@2138.19,1079
SYSREF_FPGA_P: R158.2 R163.2 U28.13 | length 897.9
  Layer 7 (SIG1) w5: v1(1691.51,1619.1) 1725.61,1585 1926.53,1585 2008,1503.53 2008,1234.24 v1(2138.19,1104.05)
  Bottom Copper w9: v1(1691.51,1619.1) R158.2@1696.51,1624.1 ; U28.13@2068.19,1094.87 2079.14,1094.87 ccw(c2079.14,1103.87) 2084.27,1096.48 2085.6,1097.4 cw(c2090.73,1090) 2090.73,1099 2133.14,1099 v1(2138.19,1104.05)
SYSREF_LMK_ADC_N: R148.2 R150.2 U2.14 | length 64.2
  Bottom Copper w10: U2.14@1824.54,1257.56 1863.36,1257.56 cw(c1863.36,1256.38) R148.2@1864.54,1256.38 1887.54,1256.38 R150.2@1887.54,1255.9
SYSREF_LMK_ADC_P: R148.1 R149.2 U2.13 | length 64.2
  Bottom Copper w10: U2.13@1824.54,1277.24 1863.36,1277.24 ccw(c1863.36,1278.42) R148.1@1864.54,1278.42 1887.54,1278.42 R149.2@1887.54,1278.9
SYSREF_LMK_FPGA_N: R159.2 R161.2 U2.61 | length 64.2
  Bottom Copper w10: U2.61@1739.9,1539.05 1739.9,1577.87 cw(c1741.08,1577.87) R159.2@1741.08,1579.05 1741.08,1602.05 R161.2@1741.56,1602.05
SYSREF_LMK_FPGA_P: R159.1 R160.2 U2.60 | length 64.2
  Bottom Copper w10: R160.2@1718.56,1602.05 1719.03,1602.05 R159.1@1719.03,1579.05 cw(c1719.03,1577.87) 1720.21,1577.87 U2.60@1720.21,1539.05
SYSREFIN_N: J10.1 R142.2 | length 411.6
  Bottom Copper w6: v1(1721.55,1059.51) 1747.81,1085.78 cw(c1769.32,1064.27) 1769.32,1094.68 1796.17,1094.68 1799.17,1094.68 ccw(c1799.17,1102.68) 1807.17,1102.68 1807.17,1119.51 cw(c1815.17,1119.51) 1823.17,1119.51 1823.17,1070.67 ccw(c1831.17,1070.67) 1839.17,1070.67 1839.17,1119.51 cw(c1847.17,1119.51) 1855.17,1119.51 1855.17,1071.21 ccw(c1863.17,1071.21) 1871.17,1071.21 1871.17,1086.68 cw(c1879.17,1086.68) 1879.17,1094.68 1895.32,1094.68 R142.2@1895.91,1094.68
SYSREFIN_P: J9.1 R129.2 | length 411.7
  Bottom Copper w6: v1(1490.45,1059.51) 1630.14,1059.51 cw(c1630.14,1018.75) 1658.94,1047.6 ; 1658.97,1047.57 ccw(c1684.6,1073.21) 1684.6,1036.96 1893.58,1036.96 cw(c1893.58,1033.67) R129.2@1895.91,1035.99
TDI_FMC: J1.D30 R70.1 | length 36.7
  Top Copper w5: v1(3900,900) 3901.79,900 3915,886.79 R70.1@3915,886
  Bottom Copper w5: v1(3900,900) 3914,900 J1.D30@3915,901
TDO_FMC: J1.D31 R70.2 | length 36.7
  Top Copper w5: v1(3900,850) 3901.83,850 3915,863.17 R70.2@3915,863.95
  Bottom Copper w5: v1(3900,850) 3914,850 J1.D31@3915,851
VADJ: J1.E39 J1.F40 J1.G39 J1.H40 PP30.1 R47.1 U17.5 U17.14 U17.15 U17.16 U19.2 U19.5 | length 703.4
  Bottom Copper w6: v1(974.49,2176.09) U19.5@992.97,2176.1 1000.25,2176.1 1019.94,2156.42 U19.2@1051.24,2156.42 ; v1(987.56,2381.27) R47.1@1008.25,2381.27 ; PP30.1@3462,475 3740,475 3765,450 3715,400 3742.77,372.23 3787.23,372.23 J1.E39@3865,450
  Bottom Copper w8: U17.5@1063.37,2312.35 v1(1083.37,2312.35)
  other v1: 953,2324 973,2324
VCM: C91.2 C92.2 U1.26 | length 73
  Top Copper w6: v1(2660,1340) 2670,1340 2704.45,1340 U1.26@2707.96,1343.51 ; U1.26@2707.96,1343.55 2709.88,1345.47 U1.26@2716.77,1345.47
  Bottom Copper w8: C91.2@2660,1326.06 v1(2660,1340)
VDDL18: C65.2 PP13.1 R56.1 R57.1 U15.1 U21.13 U22.2 U22.5 U23.13 | length 157.3
  Top Copper w6: v1(942.12,1758.6) 942.32,1758.8 962.67,1758.8 U22.2@962.87,1759 965.77,1761.91 982.17,1761.91 998.94,1778.69 U22.5@1021.13,1778.69 ; U21.13@1109.62,1697.24 1112.88,1700.5 v1(1115.21,1700.5)
  Top Copper w10: U15.1@832,1044 856.18,1044 859.29,1040.88 v1(861.46,1040.88)
  Bottom Copper w6: v1(194.27,1807.62) 196.57,1805.33 196.57,1800.93 204.38,1793.12 U23.13@204.38,1785.24 ; R56.1@994.23,2100.4 994.59,2100.4 v1(998.38,2104.19)
  other v1: 965.12,1051.87 1066.35,2030.98
pads on no net: FID1.1 FID2.1 FID3.1 H5. H6. H7.4 H8.4 J1. J3.4@101.75,378.8 J3.4@901.75,378.79 J3.MH1 J3.MH2 LBL1.0 Q1.0 Q1.0_1 SH-J7.0 SH-J8.0

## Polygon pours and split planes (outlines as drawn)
GND on Bottom Copper "GND_FLOOD_L14" (solid, remove dead copper, pour order 2258): 0,2750 4190,2750 4190,0 0,0
12V_VIN+ on Bottom Copper "12V_VIN+_L14_P2252" (solid, pour order 2252): 708.35,2259.44 807.01,2259.44 807.01,2457.02 708.35,2457.02
3p3V_Utility on Layer 12 (PWR3) "Layer 12 (PWR3)-3p3V_Utility" (solid, pour order 2332): 2094.29,1224 2471.07,1224 2471.07,1283 2094.29,1283 2094.29,2158 2962.09,2158 2961.95,2584 2094.29,2584 1241,2584 1241,2599 0,2599 0,239.02 2093,239.02 2093,374 2094.29,374
GND on Layer 12 (PWR3) "GND_FLOOD_L11" (solid, remove dead copper, pour order 2337): 0,2750 4190,2750 4190,0 0,0
VADJ on Layer 12 (PWR3) "VADJ_L12_P2317" (solid, pour order 2317): 3350,340 3350,2390 1171,2390 1171,2153 956.64,2153 955.75,2201.04 965.3,2211.6 965.16,2281.36 918,2329 918,2592 3497,2592 3497,648 3915,648 3915,340
GND on Top Copper "GND_FLOOD_L01" (solid, remove dead copper, pour order 2272): 0,2750 4190,2750 4190,0 0,0
12V on Top Copper "12V" (solid, remove dead copper, pour order 2216): 791.72,2321 930,2321 930,2395 791.72,2395
GND on Bottom Solder Mask "Exposed cooling" (solid, pour order 2330): 2763,1261 3018,1261 3018,1490 2763,1490
AVDD12 on Layer 3 (PWR1) "AVDD12_L03_P2293" (solid, remove dead copper, pour order 2293): 1175,1336.04 1175,725.86 2829.34,725.86 2829.34,1583.84 1489.9,1583.84 1489.9,1336.04
DVDD on Layer 3 (PWR1) "Layer 3 (PWR1)-DVDD" (solid, pour order 2309): 1146.5,1510.57 904.56,1511.12 902.27,1336.04 1145,1336.04 1489.9,1336.04 1489.9,1583.84 2829.34,1583.84 2829.34,1060 3530,1060 3530,2344.67 1145,2344.67
GND on Layer 3 (PWR1) "GND_FLOOD_L02" (solid, remove dead copper, pour order 2336): 0,2750 4190,2750 4190,0 0,0
VDDL18 on Layer 3 (PWR1) "Layer 3 (PWR1)-VDDL18" (solid, pour order 2312): 830,880 990,880 990,1668 1130,1668 1130,2149 890,2149 890,2178.14 564,2178.14 564,1890 130,1890 130,1330 651,1330 830,1151
12V_FMC on Layer 3 (PWR1) "12V_FMC_L03_P2292" (solid, pour order 2292): 859.04,2750 859.04,2500 3801.2,2500 3801.2,357.98 4190,357.98 4190,2750
2p7V on Layer 3 (PWR1) "2P7V_L03_P2290" (solid, pour order 2290): 830,770 830,1140 380,1140 380,770
2p1V on Layer 3 (PWR1) "Layer 3 (PWR1)-2p1V" (solid, pour order 2311): 130,500 770,500 770,590 550,590 550,770 380,770 380,1140 550,1140 550,1305 130,1305
12V_VIN+ on Layer 3 (PWR1) "12V_VIN+_L03_P2302" (solid, pour order 2302): 390,2570 390,2430 570,2430 570,2300 810,2300 810,2570
CLKVDD on Layer 9 (GND5) "CLKVDD" (solid, remove dead copper, pour order 2227): 1188.82,488.78 2784,488.78 2784,1418.11 2200.7,1417.69 2201.39,924.2 1189.31,922.42
GND on Layer 9 (GND5) "GND_FLOOD_L13" (solid, remove dead copper, pour order 2324): 0,2750 4190,2750 4190,0 0,0
AVDD18 on Layer 5 (PWR2) "AVDD18_L05_P2306" (solid, pour order 2325): 1169.01,389 1788,389 1788,659 1515,659 1515,1500 2644.34,1500 2644.34,1050 3230,1050 3230,2316 1167.82,2316
GND on Layer 5 (PWR2) "GND_FLOOD_L04" (solid, remove dead copper, pour order 2334): 0,2750 4190,2750 4190,0 0,0
12V on Layer 5 (PWR2) "12V_L05_P2282" (solid, remove dead copper, pour order 2282): -3.83,0 -3.83,2471.08 1167,2471.08 1167,0
GND on Layer 2 (GND1) "GND_FLOOD_L02" (solid, remove dead copper, pour order 2212): 0,2750 4190,2750 4190,0 0,0
GND on Layer 4 (GND2 "GND_FLOOD_L04" (solid, remove dead copper, pour order 2220): 0,2750 4190,2750 4190,0 0,0
GND on Layer 11 (GND6) "GND_FLOOD_L09" (solid, pour order 2233): 4190,0 4190,2750 0,2750 0,0
GND on Layer 13 (GND7) "GND_FLOOD_L12" (solid, remove dead copper, pour order 2244): 0,2750 4190,2750 4190,0 0,0
GND on Layer 7 (SIG1) "GND_FLOOD_L12" (solid, remove dead copper, pour order 2269): 4190,0 4190,2750 0,2750 0,0
GND on Layer 6 (GND3) "GND_FLOOD_L06" (solid, remove dead copper, pour order 2275): 0,2750 4190,2750 4190,0 0,0
GND on Layer 8 (GND4) "GND_FLOOD_L13" (solid, remove dead copper, pour order 2323): 0,2750 4190,2750 4190,0 0,0
GND on Layer 10 (SIG2) "GND_FLOOD_L03" (solid, remove dead copper, pour order 2321): 0,2750 4190,2750 4190,0 0,0

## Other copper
Top Copper:
  drawing of 126 lines, arcs and shapes, not listed
  text ".Layer_Name" at 576,-857 h60
Layer 2 (GND1):
  pour cut-out: 1665.01,2368.41 ccw(c1691.01,2368.41) 1691.01,2342.41 ccw(c1691.01,2368.41) 1717.01,2368.41 ccw(c1691.01,2368.41) 1691.01,2394.41 ccw(c1691.01,2368.41)
  pour cut-out: 2370.41,709.4 ccw(c2352.02,727.79) 2370.41,746.17 ccw(c2352.02,727.79) 2333.64,746.17 ccw(c2352.02,727.79) 2333.64,709.4 ccw(c2352.02,727.79)
  pour cut-out: 2224.4,1894.59 ccw(c2242.79,1912.98) 2261.17,1894.59 ccw(c2242.79,1912.98) 2261.17,1931.36 ccw(c2242.79,1912.98) 2224.4,1931.36 ccw(c2242.79,1912.98)
  pour cut-out: 2473.51,1421.88 2437.51,1421.88 2437.51,1491.88 2473.51,1491.88
  pour cut-out: 2473.51,1296.69 2437.51,1296.69 2437.51,1366.69 2473.51,1366.69
  pour cut-out: 2373.51,1296.69 2337.51,1296.69 2337.51,1366.69 2373.51,1366.69
  pour cut-out: 2560.98,1064.3 2535.53,1038.85 2486.03,1088.34 2511.49,1113.8
  pour cut-out: 2649.51,975.78 2624.06,950.32 2574.56,999.82 2600.01,1025.27
  pour cut-out: 2578.8,905.07 2553.34,879.61 2503.85,929.11 2529.3,954.56
  pour cut-out: 2420.06,1686.2 2394.61,1711.66 2444.11,1761.15 2469.56,1735.7
  pour cut-out: 2490.78,1615.49 2465.32,1640.94 2514.82,1690.44 2540.27,1664.99
  pour cut-out: 2579.3,1704.02 2553.85,1729.47 2603.34,1778.97 2628.8,1753.51
  text ".Layer_Name" at 579,-854 h60
Layer 5 (PWR2):
  pour cut-out: 1303.31,625.21 ccw(c1303.31,631.94) 1310.04,631.94 1310.04,650.47 1310.04,698.71 ccw(c1303.31,698.71) 1303.31,705.45 1213.31,705.45 ccw(c1213.31,698.71) 1206.57,698.71 1206.57,631.94 ccw(c1213.31,631.94) 1213.31,625.21 1241.4,625.21
  pour cut-out: 2370.41,709.4 ccw(c2352.02,727.79) 2370.41,746.17 ccw(c2352.02,727.79) 2333.64,746.17 ccw(c2352.02,727.79) 2333.64,709.4 ccw(c2352.02,727.79)
  pour cut-out: 1665.01,2368.41 ccw(c1691.01,2368.41) 1691.01,2342.41 ccw(c1691.01,2368.41) 1717.01,2368.41 ccw(c1691.01,2368.41) 1691.01,2394.41 ccw(c1691.01,2368.41)
  pour cut-out: 2224.4,1894.59 ccw(c2242.79,1912.98) 2261.17,1894.59 ccw(c2242.79,1912.98) 2261.17,1931.36 ccw(c2242.79,1912.98) 2224.4,1931.36 ccw(c2242.79,1912.98)
  pour cut-out: 2373.51,1296.69 2337.51,1296.69 2337.51,1366.69 2373.51,1366.69
  pour cut-out: 2473.51,1296.69 2437.51,1296.69 2437.51,1366.69 2473.51,1366.69
  pour cut-out: 2473.51,1421.88 2437.51,1421.88 2437.51,1491.88 2473.51,1491.88
  pour cut-out: 2578.8,905.07 2553.34,879.61 2503.85,929.11 2529.3,954.56
  pour cut-out: 2649.51,975.78 2624.06,950.32 2574.56,999.82 2600.01,1025.27
  pour cut-out: 2560.98,1064.3 2535.53,1038.85 2486.03,1088.34 2511.49,1113.8
  pour cut-out: 2579.3,1704.02 2553.85,1729.47 2603.34,1778.97 2628.8,1753.51
  pour cut-out: 2490.78,1615.49 2465.32,1640.94 2514.82,1690.44 2540.27,1664.99
  pour cut-out: 2420.06,1686.2 2394.61,1711.66 2444.11,1761.15 2469.56,1735.7
  text ".Layer_Name" at 578,-856 h60
Layer 10 (SIG2):
  pour cut-out: 1303.31,625.21 ccw(c1303.31,631.94) 1310.04,631.94 1310.04,650.47 1310.04,698.71 ccw(c1303.31,698.71) 1303.31,705.45 1213.31,705.45 ccw(c1213.31,698.71) 1206.57,698.71 1206.57,631.94 ccw(c1213.31,631.94) 1213.31,625.21 1241.4,625.21
  pour cut-out: 1073.71,1572.52 1073.71,1595.5 1050.98,1595.5 1050.98,1572.52
  pour cut-out: 165.99,2130.72 165.99,2139.72 122.85,2139.72 122.85,2130.72
  pour cut-out: 1371,1576.74 1371,1530 1503.47,1530 1549.28,1484.2 1902,1484.2 1902,1605.71 1835.71,1672 1466.26,1672
  pour cut-out: 3561.13,947.13 3676,947.13 3676,956.22 3561.13,956.22
  pour cut-out: 3561.13,947 3561.13,838.75 3570.22,838.75 3570.22,947
  pour cut-out: 374.43,1714.49 374.43,1749.69 314.27,1749.69 314.27,1714.49
  pour cut-out: 492.54,1714.49 492.54,1749.69 432.38,1749.69 432.38,1714.49
  pour cut-out: 374.43,1807.22 374.43,1842.42 314.27,1842.42 314.27,1807.22
  pour cut-out: 1121.09,1572.52 1121.09,1595.5 1098.36,1595.5 1098.36,1572.52
  pour cut-out: 2119.67,1036.67 2130.57,1025.77 2338.03,1233.24 2327.13,1244.13
  pour cut-out: 3126.01,1551.09 2897.99,1551.09 2897.99,1542 3126.01,1542
  pour cut-out: 699.14,1963.91 699.14,1986.88 676.41,1986.88 676.41,1963.91
  pour cut-out: 922.96,2088.97 922.96,2111.94 900.23,2111.94 900.23,2088.97
  pour cut-out: 3535.57,845.28 3519.32,861.53 3503.25,845.45 3519.49,829.21
  pour cut-out: 2875.63,2234.08 2875.63,2257.06 2852.9,2257.06 2852.9,2234.08
  pour cut-out: 3780.34,1063.54 3780.34,1039.69 3834.11,985.93 4055.96,985.93 4063,992.97 4063,1009.03 4055,1017.03 3854,1017.03 3807.5,1063.54
  pour cut-out: 3783,739 4063,739 4063,862.59 4032.18,862.59 3986.59,817 3837,817 3783,763
  pour cut-out: 976.36,2028.77 976.36,2051.74 953.63,2051.74 953.63,2028.77
  pour cut-out: 1021.9,1895.91 1021.9,1918.88 999.17,1918.88 999.17,1895.91
  pour cut-out: 821.4,1880.32 821.4,1903.29 798.67,1903.29 798.67,1880.32
  pour cut-out: 910.02,1948.86 910.02,1993.05 876.26,1993.05 876.26,1948.86
  pour cut-out: 492.54,1807.22 492.54,1842.42 432.38,1842.42 432.38,1807.22
  pour cut-out: 610.65,1714.49 610.65,1749.69 550.49,1749.69 550.49,1714.49
  text ".Layer_Name" at 573,-854 h60
Layer 4 (GND2:
  pour cut-out: 1665.01,2368.41 ccw(c1691.01,2368.41) 1691.01,2342.41 ccw(c1691.01,2368.41) 1717.01,2368.41 ccw(c1691.01,2368.41) 1691.01,2394.41 ccw(c1691.01,2368.41)
  pour cut-out: 2370.41,709.4 ccw(c2352.02,727.79) 2370.41,746.17 ccw(c2352.02,727.79) 2333.64,746.17 ccw(c2352.02,727.79) 2333.64,709.4 ccw(c2352.02,727.79)
  pour cut-out: 2224.4,1894.59 ccw(c2242.79,1912.98) 2261.17,1894.59 ccw(c2242.79,1912.98) 2261.17,1931.36 ccw(c2242.79,1912.98) 2224.4,1931.36 ccw(c2242.79,1912.98)
  pour cut-out: 2373.51,1296.69 2337.51,1296.69 2337.51,1366.69 2373.51,1366.69
  pour cut-out: 2473.51,1296.69 2437.51,1296.69 2437.51,1366.69 2473.51,1366.69
  pour cut-out: 2473.51,1421.88 2437.51,1421.88 2437.51,1491.88 2473.51,1491.88
  pour cut-out: 2578.8,905.07 2553.34,879.61 2503.85,929.11 2529.3,954.56
  pour cut-out: 2649.51,975.78 2624.06,950.32 2574.56,999.82 2600.01,1025.27
  pour cut-out: 2560.98,1064.3 2535.53,1038.85 2486.03,1088.34 2511.49,1113.8
  pour cut-out: 2579.3,1704.02 2553.85,1729.47 2603.34,1778.97 2628.8,1753.51
  pour cut-out: 2490.78,1615.49 2465.32,1640.94 2514.82,1690.44 2540.27,1664.99
  pour cut-out: 2420.06,1686.2 2394.61,1711.66 2444.11,1761.15 2469.56,1735.7
  text ".Layer_Name" at 579,-854 h60
Layer 3 (PWR1):
  pour cut-out: 1303.31,625.21 ccw(c1303.31,631.94) 1310.04,631.94 1310.04,650.47 1310.04,698.71 ccw(c1303.31,698.71) 1303.31,705.45 1213.31,705.45 ccw(c1213.31,698.71) 1206.57,698.71 1206.57,631.94 ccw(c1213.31,631.94) 1213.31,625.21 1241.4,625.21
  pour cut-out: 1569.37,924.41 ccw(c1490.65,924.41) 1490.65,1003.13 ccw(c1490.65,924.41) 1411.93,924.41 ccw(c1490.65,924.41) 1490.65,845.69 ccw(c1490.65,924.41)
  pour cut-out: 1800.47,924.41 ccw(c1721.75,924.41) 1721.75,1003.13 ccw(c1721.75,924.41) 1643.03,924.41 ccw(c1721.75,924.41) 1721.75,845.69 ccw(c1721.75,924.41)
  pour cut-out: 2370.41,709.4 ccw(c2352.02,727.79) 2370.41,746.17 ccw(c2352.02,727.79) 2333.64,746.17 ccw(c2352.02,727.79) 2333.64,709.4 ccw(c2352.02,727.79)
  pour cut-out: 1665.01,2368.41 ccw(c1691.01,2368.41) 1691.01,2342.41 ccw(c1691.01,2368.41) 1717.01,2368.41 ccw(c1691.01,2368.41) 1691.01,2394.41 ccw(c1691.01,2368.41)
  pour cut-out: 2224.4,1894.59 ccw(c2242.79,1912.98) 2261.17,1894.59 ccw(c2242.79,1912.98) 2261.17,1931.36 ccw(c2242.79,1912.98) 2224.4,1931.36 ccw(c2242.79,1912.98)
  pour cut-out: 2373.51,1296.69 2337.51,1296.69 2337.51,1366.69 2373.51,1366.69
  pour cut-out: 2473.51,1296.69 2437.51,1296.69 2437.51,1366.69 2473.51,1366.69
  pour cut-out: 2473.51,1421.88 2437.51,1421.88 2437.51,1491.88 2473.51,1491.88
  pour cut-out: 1451.15,991.51 1529.75,991.51 1529.75,1026.81 1451.15,1026.81
  pour cut-out: 1682.25,991.51 1760.85,991.51 1760.85,1026.81 1682.25,1026.81
  pour cut-out: 1477.45,1072.01 1477.45,1017.01 1503.45,1017.01 1503.45,1072.01
  pour cut-out: 1708.55,1072.01 1708.55,1017.01 1734.55,1017.01 1734.55,1072.01
  pour cut-out: 2578.8,905.07 2553.34,879.61 2503.85,929.11 2529.3,954.56
  pour cut-out: 2649.51,975.78 2624.06,950.32 2574.56,999.82 2600.01,1025.27
  pour cut-out: 2560.98,1064.3 2535.53,1038.85 2486.03,1088.34 2511.49,1113.8
  pour cut-out: 2579.3,1704.02 2553.85,1729.47 2603.34,1778.97 2628.8,1753.51
  pour cut-out: 2490.78,1615.49 2465.32,1640.94 2514.82,1690.44 2540.27,1664.99
  pour cut-out: 2420.06,1686.2 2394.61,1711.66 2444.11,1761.15 2469.56,1735.7
  text ".Layer_Name" at 576,-856 h60
Layer 6 (GND3):
  text ".Layer_Name" at 573,-856 h60
Layer 12 (PWR3):
  pour cut-out: 1303.31,625.21 ccw(c1303.31,631.94) 1310.04,631.94 1310.04,650.47 1310.04,698.71 ccw(c1303.31,698.71) 1303.31,705.45 1213.31,705.45 ccw(c1213.31,698.71) 1206.57,698.71 1206.57,631.94 ccw(c1213.31,631.94) 1213.31,625.21 1241.4,625.21
  text ".Layer_Name" at 581,-856 h60
Layer 11 (GND6):
  text ".Layer_Name" at 576,-857 h60
Layer 8 (GND4):
  text ".Layer_Name" at 577,-852 h60
Layer 9 (GND5):
  text ".Layer_Name" at 583,-850 h60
